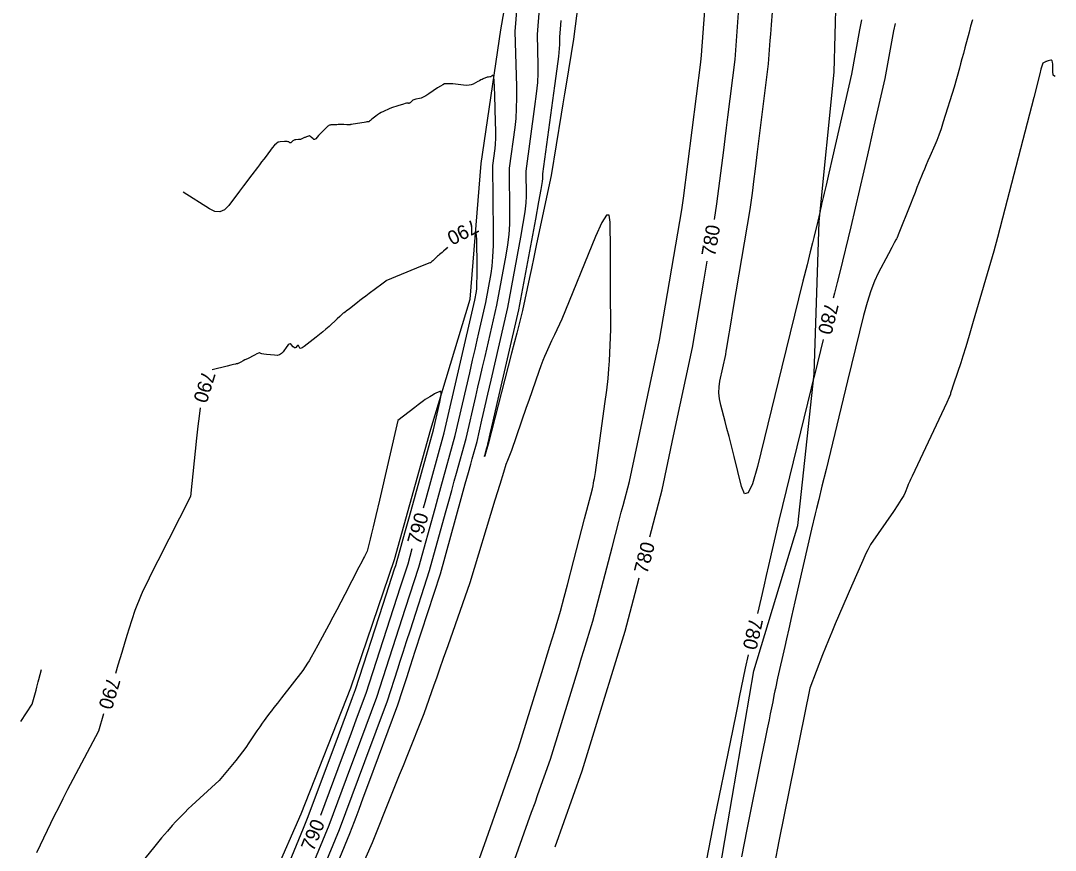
# Model space of a CAD drawing. Extents: x -26 to 1809989, y -25 to 828749.
# Drawn here: x 1809612.6 to 1809979.9, y 827324 to 827618.3 of the extents above; entities that cross this region are included whole.
import ezdxf

# ---------------------------------------------------------------- set-up
doc = ezdxf.new("R2010")
doc.units = 0
for name, color, linetype in [('DESIGN - CONTOURS - Index with Text', 7, 'Continuous'), ('DESIGN - CONTOURS - Intermediate with optional Text', 7, 'Continuous'), ('DESIGN - ROW - Slope Lines', 7, 'Continuous')]:
    doc.layers.add(name, color=color, linetype=linetype)

msp = doc.modelspace()

# ---------------------------------------------------------------- linework, layer by layer
at = {"layer": 'DESIGN - CONTOURS - Index with Text'}
for points in [[(1809858.86, 827547.81), (1809859.8, 827553.36), (1809862.18, 827572.38), (1809862.68, 827576.39), (1809863.17, 827580.29), (1809863.64, 827584.08), (1809866.22, 827604.57), (1809867.83, 827626.21), (1809868.17, 827630.65), (1809868.47, 827634.7), (1809868.74, 827638.36), (1809868.99, 827641.63), (1809869.41, 827647.21)], [(1809923.03, 827617.38), (1809922.5, 827614.75), (1809919.4, 827597.83), (1809915.52, 827580.87), (1809914.67, 827577.16), (1809913.78, 827573.29), (1809911.9, 827565.09), (1809907.33, 827545.22), (1809903.36, 827529.07), (1809902.49, 827525.49), (1809901.55, 827521.69), (1809901.1, 827519.84)], [(1809755.62, 827445.49), (1809756.19, 827447.55), (1809763, 827472.14), (1809773.83, 827519.15), (1809774.41, 827522.28), (1809774.52, 827523.32), (1809774.58, 827525.12), (1809774.61, 827527.67), (1809774.6, 827530.98), (1809774.53, 827540.8), (1809774.33, 827543.19)], [(1809764.17, 827537.96), (1809763.61, 827537.41), (1809762.74, 827536.59), (1809762.23, 827536.13), (1809761.3, 827535.37), (1809760.96, 827535.08), (1809760.6, 827534.78), (1809760.24, 827534.45), (1809759.88, 827534.11), (1809758.9, 827533.19), (1809758.58, 827532.88), (1809758.34, 827532.66), (1809758.19, 827532.52), (1809758.13, 827532.46), (1809758.08, 827532.42), (1809758.05, 827532.41), (1809758.03, 827532.4), (1809758, 827532.39), (1809757.96, 827532.39), (1809757.87, 827532.4), (1809757.54, 827532.28), (1809756.65, 827531.92), (1809755.18, 827531.32), (1809753.13, 827530.48), (1809742.26, 827525.99), (1809742.21, 827525.97), (1809742.2, 827525.96), (1809742.18, 827525.95), (1809740.76, 827524.88), (1809736.3, 827521.53), (1809735.1, 827520.62), (1809734, 827519.79), (1809733.01, 827519.03), (1809732.13, 827518.34), (1809729.93, 827516.61), (1809729.18, 827516.03), (1809728.6, 827515.58), (1809728.17, 827515.26), (1809727.91, 827515.07), (1809727.43, 827514.74), (1809727.13, 827514.51), (1809726.62, 827514.06), (1809725.88, 827513.39), (1809724.92, 827512.5), (1809722.07, 827509.85), (1809720.98, 827508.86), (1809719.86, 827507.89), (1809718.72, 827506.94), (1809717.54, 827506.01), (1809714.35, 827503.54), (1809713.29, 827502.77), (1809712.49, 827502.28), (1809711.96, 827502.09), (1809711.68, 827502.19), (1809711.31, 827502.85), (1809711.17, 827503.04), (1809711.02, 827503.11), (1809710.86, 827503.08), (1809710.7, 827502.94), (1809710.25, 827502.4), (1809710.07, 827502.26), (1809709.86, 827502.26), (1809709.63, 827502.38), (1809709.36, 827502.64), (1809708.62, 827503.49), (1809708.31, 827503.69), (1809707.95, 827503.62), (1809707.54, 827503.29), (1809707.08, 827502.71), (1809705.78, 827500.81), (1809705.22, 827500.2), (1809704.51, 827499.8), (1809703.67, 827499.6), (1809702.68, 827499.62), (1809699.86, 827499.94), (1809698.93, 827500.05), (1809698.25, 827500.15), (1809697.82, 827500.25), (1809697.65, 827500.33), (1809697.52, 827500.53), (1809697.37, 827500.54), (1809696.99, 827500.4), (1809696.38, 827500.13), (1809695.56, 827499.71), (1809693.06, 827498.42), (1809692.21, 827497.97), (1809691.54, 827497.62), (1809690.71, 827497.19), (1809690.08, 827496.85), (1809689.86, 827496.74), (1809689.67, 827496.66), (1809689.51, 827496.6), (1809689.39, 827496.58), (1809689.1, 827496.55), (1809688.82, 827496.5), (1809688.2, 827496.36), (1809687.24, 827496.13), (1809685.94, 827495.82), (1809680.55, 827494.52)], [(1809835.94, 827435.17), (1809840.29, 827451.86), (1809844.41, 827471.03), (1809851.16, 827502.42), (1809855.14, 827525.9), (1809856.35, 827533.02)], [(1809897.51, 827505.27), (1809894.51, 827493.04), (1809894.27, 827492.06), (1809893.99, 827490.93), (1809893.26, 827487.95), (1809881.78, 827440.98), (1809878.11, 827425.01), (1809877.3, 827421.46), (1809876.43, 827417.66), (1809875.5, 827413.6), (1809874.22, 827408.02)], [(1809676.37, 827480.97), (1809675.92, 827478.05), (1809675.46, 827474.43), (1809674.99, 827470.26), (1809672.83, 827449.54), (1809661.29, 827426.74), (1809659.06, 827422.32), (1809657.34, 827418.82), (1809656.11, 827416.25), (1809655.38, 827414.6), (1809653.14, 827409.06), (1809651.02, 827402.48), (1809650.43, 827400.62), (1809649.59, 827397.86), (1809648.49, 827394.2), (1809647.12, 827389.65), (1809646.26, 827386.76)], [(1809719.12, 827336.5), (1809726.81, 827357.1), (1809729.88, 827365.35), (1809731.87, 827370.68), (1809735.23, 827379.69), (1809747.47, 827417.45), (1809750.12, 827425.62), (1809751.62, 827431.03)], [(1809802.37, 827325.25), (1809811.98, 827352.24), (1809815.28, 827362.95), (1809827.23, 827401.77), (1809830.74, 827415.24), (1809832.15, 827420.66)], [(1809870.88, 827393.4), (1809869.78, 827388.6), (1809867.7, 827378.36), (1809867.16, 827375.72), (1809866.44, 827372.18), (1809864.45, 827362.41), (1809858.96, 827335.44), (1809856.09, 827320.79), (1809855.43, 827317.43), (1809854.68, 827313.61), (1809852.93, 827304.59), (1809851.13, 827295.37)], [(1809641.97, 827372.39), (1809640.16, 827366.31), (1809631.12, 827349.16), (1809629.26, 827345.59), (1809627.54, 827342.24), (1809625.96, 827339.11), (1809624.52, 827336.19), (1809618.16, 827323.09)]]:
    msp.add_lwpolyline(points, dxfattribs=at)
at = {"layer": 'DESIGN - CONTOURS - Intermediate with optional Text'}
for points in [[(1809783.47, 827307.9), (1809793.98, 827337.47), (1809795.19, 827340.86), (1809796.23, 827343.78), (1809800.68, 827356.28), (1809808.02, 827380.13), (1809810.72, 827388.92), (1809811.74, 827392.24), (1809812.54, 827394.84), (1809815.76, 827405.31), (1809822.56, 827431.4), (1809824.98, 827440.71), (1809825.83, 827443.96), (1809826.44, 827446.28), (1809828.69, 827454.9), (1809838.11, 827498.85), (1809839.43, 827504.96), (1809847.28, 827551.27), (1809847.97, 827555.39), (1809854.01, 827603.66), (1809854.31, 827606.08), (1809858.12, 827656.98)], [(1809706.9, 827285.55), (1809725.76, 827331.42), (1809734.76, 827355.54), (1809742.77, 827377), (1809746.46, 827388.39), (1809747.33, 827391.09), (1809748.37, 827394.3), (1809749.58, 827398.03), (1809750.96, 827402.27), (1809757.77, 827423.26), (1809763.43, 827443.72), (1809764.59, 827447.89), (1809765.62, 827451.62), (1809766.53, 827454.92), (1809767.32, 827457.78), (1809770.74, 827470.11), (1809774.16, 827484.99), (1809774.92, 827488.27), (1809775.72, 827491.73), (1809776.56, 827495.37), (1809777.44, 827499.19), (1809781.65, 827517.46), (1809784.92, 827535.11), (1809785.53, 827538.85), (1809785.96, 827542.53), (1809786.2, 827546.13), (1809786.27, 827549.66), (1809786.14, 827565.97), (1809788.11, 827580.4), (1809788.46, 827583.63), (1809788.68, 827587.13), (1809788.75, 827590.91), (1809788.69, 827594.95), (1809788.09, 827614.48), (1809790.79, 827646.8)], [(1809717.77, 827301.46), (1809729.47, 827329.91), (1809731.09, 827334.25), (1809731.67, 827335.81), (1809732.71, 827338.61), (1809734.23, 827342.67), (1809736.21, 827347.97), (1809746.53, 827375.65), (1809748.19, 827380.75), (1809748.73, 827382.44), (1809749.67, 827385.33), (1809750.99, 827389.41), (1809752.7, 827394.68), (1809761.59, 827422.07), (1809768.98, 827448.79), (1809770.42, 827453.96), (1809771.55, 827458.04), (1809772.37, 827461.02), (1809772.89, 827462.9), (1809774.6, 827469.09), (1809776.33, 827476.57), (1809776.81, 827478.67), (1809777.52, 827481.74), (1809778.45, 827485.8), (1809779.62, 827490.83), (1809785.56, 827516.62), (1809790.18, 827541.52), (1809791.04, 827546.43), (1809791.65, 827550.49), (1809792.01, 827553.68), (1809792.12, 827556.03), (1809792.05, 827564.96), (1809795.18, 827587.84), (1809795.75, 827592.43), (1809796.14, 827596.38), (1809796.35, 827599.71), (1809796.37, 827602.4), (1809796.02, 827613.47), (1809797.55, 827631.81)], [(1809810.51, 827624.65), (1809808.9, 827611.84), (1809806.25, 827595.86), (1809805.67, 827592.38), (1809805.08, 827588.81), (1809804.47, 827585.13), (1809800.88, 827563.45), (1809795.77, 827539.21), (1809794.76, 827534.42), (1809793.92, 827530.42), (1809793.25, 827527.22), (1809790.77, 827515.49), (1809789.19, 827509.32), (1809788.71, 827507.44), (1809787.94, 827504.44), (1809786.88, 827500.33), (1809778.6, 827468.04), (1809777.51, 827464.44), (1809777.33, 827463.85), (1809777.26, 827463.66), (1809777.3, 827463.85), (1809777.46, 827464.42), (1809778.02, 827466.45), (1809778.21, 827467.12), (1809778.34, 827467.61), (1809778.43, 827467.9), (1809778.45, 827468.01), (1809778.47, 827468.08), (1809778.49, 827468.16), (1809778.7, 827469.07), (1809779.32, 827471.75), (1809780.35, 827476.22), (1809781.79, 827482.47), (1809789.47, 827515.77), (1809795.43, 827547.94), (1809796.55, 827554.01), (1809797.35, 827558.45), (1809797.82, 827561.24), (1809797.98, 827562.39), (1809797.97, 827563.95), (1809802.24, 827595.28), (1809803.04, 827601.23), (1809803.61, 827605.64), (1809803.94, 827608.51), (1809804.04, 827609.84), (1809803.96, 827612.47), (1809804.32, 827616.82), (1809804.46, 827618.43)], [(1809911.1, 827618.64), (1809910.45, 827615.12), (1809907.55, 827599.33), (1809900.79, 827569.89), (1809899.49, 827564.26), (1809898.51, 827560), (1809897.84, 827557.09), (1809897.49, 827555.55), (1809896.96, 827553.25), (1809896.77, 827552.41), (1809896.59, 827551.63), (1809896.42, 827550.91), (1809896.27, 827550.24), (1809895.58, 827547.23), (1809894.14, 827541.41), (1809893.67, 827539.51), (1809892.88, 827536.29), (1809891.76, 827531.76), (1809890.32, 827525.91), (1809882.83, 827495.57), (1809874.17, 827460.2), (1809872.43, 827454.07), (1809870.9, 827450.83), (1809869.58, 827450.48), (1809868.49, 827453.03), (1809865.85, 827463.68), (1809864.92, 827467.45), (1809864.08, 827470.77), (1809863.34, 827473.65), (1809862.71, 827476.08), (1809861.15, 827481.97), (1809860.7, 827484.16), (1809860.49, 827486.3), (1809860.55, 827488.39), (1809860.85, 827490.44), (1809862.89, 827499.89), (1809863.09, 827501.08), (1809863.28, 827502.24), (1809863.79, 827505.2), (1809864.6, 827509.96), (1809865.71, 827516.52), (1809871.63, 827551.33), (1809872.25, 827556.3), (1809872.47, 827558.07), (1809872.87, 827561.24), (1809873.45, 827565.83), (1809874.2, 827571.82), (1809878.12, 827603.06), (1809878.74, 827611.26), (1809878.91, 827613.56), (1809879.16, 827616.92), (1809879.49, 827621.35)], [(1809950.46, 827618.59), (1809949.86, 827616.4), (1809949.29, 827614.27), (1809947.81, 827608.66), (1809947.27, 827606.64), (1809946.77, 827604.78), (1809946.31, 827603.08), (1809945.89, 827601.53), (1809944.02, 827594.71), (1809940.15, 827582.46), (1809939.34, 827579.98), (1809938.56, 827577.77), (1809937.82, 827575.83), (1809937.13, 827574.17), (1809935.31, 827570.11), (1809934.65, 827568.61), (1809934.02, 827567.14), (1809933.42, 827565.71), (1809932.86, 827564.31), (1809931.4, 827560.63), (1809930.8, 827559.13), (1809930.12, 827557.4), (1809929.33, 827555.42), (1809928.45, 827553.21), (1809924.14, 827542.34), (1809923.84, 827541.62), (1809923.78, 827541.48), (1809923.73, 827541.35), (1809923.67, 827541.25), (1809923.62, 827541.16), (1809923.5, 827540.95), (1809923.29, 827540.56), (1809922.75, 827539.55), (1809921.88, 827537.92), (1809920.68, 827535.66), (1809917.04, 827528.8), (1809915.69, 827525.93), (1809914.38, 827522.46), (1809913.1, 827518.39), (1809911.87, 827513.72), (1809906.18, 827490.52), (1809898.53, 827459.16), (1809897.06, 827453.14), (1809895.93, 827448.5), (1809895.14, 827445.25), (1809894.68, 827443.39), (1809893.36, 827437.94), (1809887.47, 827412.12), (1809886.3, 827406.98), (1809885.31, 827402.62), (1809884.49, 827399.04), (1809883.85, 827396.25), (1809881.29, 827385.04), (1809880.56, 827381.44), (1809880.38, 827380.56), (1809880.16, 827379.47), (1809879.9, 827378.18), (1809879.59, 827376.68), (1809878.72, 827372.39), (1809878.29, 827370.28), (1809877.65, 827367.14), (1809876.81, 827363), (1809875.76, 827357.83), (1809870.37, 827331.35), (1809868.48, 827321.68)], [(1809979.92, 827598.56), (1809979.3, 827598.85), (1809979.18, 827599.01), (1809979.1, 827599.36), (1809979.04, 827599.91), (1809979.02, 827600.65), (1809979, 827602.87), (1809978.95, 827603.59), (1809978.82, 827604.08), (1809978.6, 827604.33), (1809978.3, 827604.35), (1809977.38, 827604.08), (1809977.06, 827603.99), (1809976.81, 827603.9), (1809976.61, 827603.83), (1809976.47, 827603.77), (1809976.18, 827603.62), (1809975.96, 827603.5), (1809975.75, 827603.39), (1809975.47, 827603.24), (1809975.33, 827602.96), (1809975.1, 827602.25), (1809974.79, 827601.1), (1809974.39, 827599.52), (1809972.34, 827591.12), (1809961.99, 827551.46), (1809959.38, 827541.46), (1809958.09, 827536.53), (1809950.8, 827511.61), (1809949.35, 827506.69), (1809948.12, 827502.6), (1809947.11, 827499.34), (1809946.32, 827496.91), (1809943.92, 827489.74), (1809943.46, 827488.37), (1809943.15, 827487.43), (1809942.99, 827486.92), (1809942.75, 827486.13), (1809942.65, 827485.82), (1809942.53, 827485.49), (1809942.38, 827485.13), (1809942.22, 827484.75), (1809941.39, 827482.9), (1809929.04, 827456.68), (1809928.48, 827455.51), (1809928.26, 827455.02), (1809928.01, 827454.44), (1809927.73, 827453.78), (1809927.43, 827453.02), (1809926.58, 827450.89), (1809926.09, 827449.87), (1809925.23, 827448.43), (1809924.02, 827446.55), (1809922.46, 827444.24), (1809914.32, 827432.44), (1809913.56, 827431.13), (1809913.31, 827430.65), (1809912.91, 827429.78), (1809912.34, 827428.53), (1809911.62, 827426.87), (1809907.61, 827417.69), (1809901.78, 827404.34), (1809900.53, 827401.41), (1809899.36, 827398.6), (1809898.27, 827395.9), (1809897.27, 827393.31), (1809892.8, 827381.48), (1809881.79, 827327.27), (1809880.22, 827319.21)], [(1809703.22, 827287.11), (1809722.06, 827332.93), (1809728.23, 827349.48), (1809733.31, 827363.11), (1809739, 827378.34), (1809749.21, 827409.86), (1809753.94, 827424.44), (1809759.69, 827445.21), (1809760.7, 827448.82), (1809761.76, 827452.66), (1809766.87, 827471.12), (1809772, 827493.4), (1809773.03, 827497.87), (1809773.92, 827501.71), (1809774.66, 827504.94), (1809775.26, 827507.56), (1809777.74, 827518.31), (1809779.67, 827528.69), (1809780.02, 827531.27), (1809780.27, 827534.57), (1809780.4, 827538.58), (1809780.41, 827543.3), (1809780.23, 827566.99), (1809781.04, 827572.96), (1809781.18, 827574.52), (1809781.25, 827576.62), (1809781.25, 827579.28), (1809781.17, 827582.49), (1809780.89, 827591.77), (1809780.78, 827594.82), (1809780.67, 827597.01), (1809780.57, 827598.33), (1809780.47, 827598.79), (1809780.2, 827598.85), (1809780.1, 827598.86), (1809780.01, 827598.85), (1809779.94, 827598.81), (1809779.87, 827598.74), (1809779.71, 827598.54), (1809779.63, 827598.48), (1809779.52, 827598.43), (1809779.38, 827598.39), (1809779.21, 827598.38), (1809778.7, 827598.35), (1809778.49, 827598.33), (1809778.25, 827598.27), (1809777.97, 827598.18), (1809777.66, 827598.05), (1809776.8, 827597.68), (1809776.44, 827597.52), (1809776, 827597.31), (1809775.49, 827597.05), (1809774.9, 827596.74), (1809773.23, 827595.85), (1809772.55, 827595.58), (1809771.76, 827595.42), (1809770.86, 827595.37), (1809769.85, 827595.44), (1809767, 827595.77), (1809766.06, 827595.88), (1809765.38, 827595.95), (1809764.95, 827595.98), (1809764.78, 827595.98), (1809764.67, 827595.92), (1809764.62, 827595.9), (1809764.57, 827595.89), (1809764.5, 827595.88), (1809764.42, 827595.89), (1809764.2, 827595.91), (1809764.11, 827595.92), (1809764, 827595.93), (1809763.87, 827595.94), (1809763.72, 827595.95), (1809763.3, 827595.97), (1809763.02, 827595.89), (1809762.47, 827595.61), (1809761.68, 827595.13), (1809760.63, 827594.46), (1809757.48, 827592.4), (1809756.39, 827591.72), (1809755.48, 827591.21), (1809754.74, 827590.87), (1809754.19, 827590.7), (1809752.94, 827590.49), (1809752.5, 827590.39), (1809752.12, 827590.26), (1809751.81, 827590.09), (1809751.55, 827589.9), (1809750.94, 827589.33), (1809750.73, 827589.14), (1809750.58, 827589.01), (1809750.48, 827588.94), (1809750.42, 827588.93), (1809750.35, 827588.98), (1809750.31, 827588.99), (1809750.28, 827589.01), (1809750.23, 827589.03), (1809750.18, 827589.05), (1809750.03, 827589.09), (1809749.89, 827589.08), (1809749.58, 827589.02), (1809749.1, 827588.9), (1809748.45, 827588.72), (1809746.48, 827588.17), (1809745.74, 827587.95), (1809744.99, 827587.69), (1809744.22, 827587.39), (1809743.45, 827587.06), (1809741.38, 827586.12), (1809740.63, 827585.75), (1809739.94, 827585.37), (1809739.31, 827584.96), (1809738.73, 827584.52), (1809737.27, 827583.34), (1809736.78, 827582.95), (1809736.4, 827582.67), (1809736.14, 827582.5), (1809735.98, 827582.45), (1809735.7, 827582.44), (1809735.5, 827582.43), (1809735.11, 827582.37), (1809734.53, 827582.27), (1809733.75, 827582.14), (1809731.42, 827581.74), (1809730.65, 827581.6), (1809730.08, 827581.51), (1809729.71, 827581.45), (1809729.55, 827581.43), (1809729.38, 827581.43), (1809729.28, 827581.43), (1809729.08, 827581.43), (1809728.8, 827581.43), (1809728.43, 827581.43), (1809727.31, 827581.45), (1809726.94, 827581.45), (1809726.64, 827581.45), (1809726.42, 827581.46), (1809726.28, 827581.47), (1809726.02, 827581.48), (1809725.87, 827581.48), (1809725.61, 827581.48), (1809725.26, 827581.46), (1809724.81, 827581.44), (1809723.47, 827581.38), (1809723.02, 827581.36), (1809722.67, 827581.33), (1809722.42, 827581.3), (1809722.28, 827581.27), (1809722.02, 827581.18), (1809721.88, 827581.09), (1809721.62, 827580.87), (1809721.25, 827580.53), (1809720.77, 827580.06), (1809718.29, 827577.59), (1809717.33, 827576.44), (1809717.12, 827576.25), (1809716.9, 827576.18), (1809716.66, 827576.23), (1809716.41, 827576.39), (1809715.74, 827576.99), (1809715.51, 827577.19), (1809715.35, 827577.33), (1809715.26, 827577.42), (1809715.22, 827577.45), (1809715.22, 827577.47), (1809715.18, 827577.47), (1809715.09, 827577.44), (1809714.95, 827577.4), (1809714.74, 827577.33), (1809714.12, 827577.12), (1809713.88, 827577.03), (1809713.64, 827576.94), (1809713.4, 827576.84), (1809713.14, 827576.73), (1809712.46, 827576.42), (1809712.19, 827576.32), (1809711.9, 827576.24), (1809711.58, 827576.18), (1809711.23, 827576.15), (1809710.28, 827576.09), (1809709.94, 827576.05), (1809709.66, 827575.97), (1809709.42, 827575.85), (1809709.23, 827575.68), (1809708.78, 827575.19), (1809708.61, 827575.04), (1809708.45, 827574.97), (1809708.3, 827574.96), (1809708.15, 827575.03), (1809707.76, 827575.3), (1809707.55, 827575.39), (1809707.24, 827575.44), (1809706.81, 827575.47), (1809706.27, 827575.46), (1809704.69, 827575.39), (1809704.06, 827575.23), (1809703.39, 827574.81), (1809702.65, 827574.13), (1809701.87, 827573.18), (1809699.69, 827570.31), (1809698.89, 827569.25), (1809698.11, 827568.21), (1809697.35, 827567.2), (1809696.61, 827566.22), (1809694.67, 827563.65), (1809693.85, 827562.57), (1809692.86, 827561.25), (1809691.68, 827559.69), (1809690.33, 827557.89), (1809686.48, 827552.79), (1809684.97, 827551.27), (1809683.31, 827550.56), (1809681.52, 827550.64), (1809679.59, 827551.53), (1809670.24, 827557.53)], [(1809772.35, 827312.43), (1809777.92, 827328.08), (1809783.03, 827342.45), (1809789.38, 827360.32), (1809797.61, 827387.1), (1809800.49, 827396.47), (1809802.09, 827401.66), (1809804.3, 827408.86), (1809805.59, 827413.81), (1809806.72, 827418.15), (1809809, 827426.92), (1809812.82, 827441.57), (1809814.07, 827446.42), (1809814.99, 827449.99), (1809815.57, 827452.28), (1809815.81, 827453.29), (1809815.99, 827454.27), (1809816.13, 827455.05), (1809816.29, 827455.92), (1809816.67, 827458.06), (1809820.02, 827482.4), (1809820.65, 827487.26), (1809821.14, 827491.42), (1809821.46, 827494.86), (1809821.63, 827497.6), (1809822.06, 827508.72), (1809822.02, 827523.36), (1809822, 827526.57), (1809821.99, 827529.92), (1809821.97, 827533.4), (1809821.94, 827537.03), (1809821.88, 827546.89), (1809821.53, 827549.34), (1809820.55, 827549.3), (1809818.93, 827546.77), (1809816.68, 827541.74), (1809804.66, 827512.48), (1809802.09, 827506.89), (1809801.1, 827504.75), (1809799.14, 827500.53), (1809798.58, 827499.25), (1809797.96, 827497.72), (1809797.28, 827495.93), (1809796.56, 827493.89), (1809792.95, 827483.53), (1809792.08, 827481.04), (1809786.79, 827465.9), (1809785.37, 827462.34), (1809784.87, 827460.89), (1809783.96, 827458.05), (1809782.65, 827453.83), (1809780.94, 827448.23), (1809772.03, 827418.84), (1809764.19, 827396.53), (1809762.62, 827392.07), (1809761.28, 827388.26), (1809760.17, 827385.1), (1809759.29, 827382.59), (1809755.69, 827372.37), (1809749.64, 827357.28), (1809748.33, 827354), (1809746.97, 827350.63), (1809745.58, 827347.15), (1809744.14, 827343.58), (1809737.37, 827326.69), (1809732.43, 827315.46)], [(1809695.85, 827290.23), (1809712.96, 827331.83), (1809714.65, 827335.95), (1809725.38, 827364.72), (1809729.94, 827376.95), (1809730.42, 827378.25), (1809731.47, 827381.04), (1809741.28, 827411.31), (1809745.36, 827423.89), (1809745.73, 827425.03), (1809746.3, 827426.8), (1809746.78, 827428.53), (1809749.02, 827436.63), (1809750.63, 827442.43), (1809759.13, 827473.15), (1809761.4, 827483.02), (1809761.77, 827484.84), (1809761.88, 827486.08), (1809761.75, 827486.72), (1809761.37, 827486.78), (1809760.03, 827486.17), (1809759.52, 827485.92), (1809758.98, 827485.62), (1809758.42, 827485.29), (1809757.83, 827484.92), (1809756.24, 827483.88), (1809755.56, 827483.41), (1809754.71, 827482.79), (1809753.69, 827482.02), (1809752.5, 827481.1), (1809746.54, 827476.46), (1809739.98, 827448.24), (1809738.72, 827442.84), (1809737.75, 827438.72), (1809737.08, 827435.89), (1809736.69, 827434.35), (1809735.57, 827430.13), (1809734.66, 827428.29), (1809734.31, 827427.61), (1809733.66, 827426.34), (1809732.7, 827424.49), (1809727.66, 827414.79), (1809726.24, 827412.07), (1809724.81, 827409.36), (1809723.38, 827406.66), (1809721.95, 827403.97), (1809718.1, 827396.82), (1809716.8, 827394.4), (1809715.76, 827392.52), (1809714.98, 827391.16), (1809714.47, 827390.34), (1809712.72, 827387.74), (1809705.19, 827378.09), (1809703.72, 827376.19), (1809702.52, 827374.65), (1809701.61, 827373.46), (1809700.97, 827372.63), (1809699.65, 827370.87), (1809699.08, 827370.09), (1809698.36, 827369.08), (1809697.5, 827367.83), (1809696.48, 827366.35), (1809693.58, 827362.09), (1809692.48, 827360.51), (1809691.33, 827358.94), (1809690.14, 827357.4), (1809688.92, 827355.87), (1809683.1, 827348.8), (1809676.17, 827342.55), (1809674.72, 827341.23), (1809673.36, 827339.94), (1809672.07, 827338.68), (1809670.86, 827337.46), (1809667.73, 827334.24), (1809666.38, 827332.78), (1809664.67, 827330.82), (1809662.6, 827328.37), (1809660.17, 827325.41), (1809648.02, 827310.46)], [(1809612.59, 827369.68), (1809616.7, 827375.87), (1809618.06, 827380.86), (1809618.33, 827381.89), (1809618.59, 827382.85), (1809618.82, 827383.74), (1809619.02, 827384.55), (1809619.93, 827388.18)]]:
    msp.add_lwpolyline(points, dxfattribs=at)
at = {"layer": 'DESIGN - ROW - Slope Lines'}
for p, q in [((1809783.11, 827615.11), (1809791.39, 827662.51)), ((1809901.36, 827600.12), (1809902.93, 827653.27)), ((1809776.05, 827567.7), (1809783.11, 827615.11)), ((1809896.13, 827547.14), (1809901.36, 827600.12)), ((1809772.15, 827519.52), (1809776.05, 827567.7)), ((1809894.32, 827493.08), (1809896.13, 827547.14)), ((1809758.18, 827473.4), (1809772.15, 827519.52)), ((1809888.53, 827439.21), (1809894.32, 827493.08)), ((1809745.25, 827427.13), (1809758.18, 827473.4)), ((1809872.85, 827387.65), (1809888.53, 827439.21)), ((1809729.77, 827381.64), (1809745.25, 827427.13)), ((1809863.66, 827333.75), (1809872.85, 827387.65)), ((1809712.14, 827336.97), (1809729.77, 827381.64)), ((1809692.33, 827291.71), (1809712.14, 827336.97)), ((1809854.25, 827279.05), (1809863.66, 827333.75))]:
    msp.add_line(p, q, dxfattribs=at)

# ---------------------------------------------------------------- texts
at = {"layer": 'DESIGN - CONTOURS - Index with Text'}
for s, rotation, p in [('790', 207.2362, (1809773.39, 827548.04)), ('780', 80.3548, (1809859.12, 827534.42)), ('780', 256.189, (1809898.23, 827518.64)), ('790', 252.8418, (1809677.12, 827494.47)), ('790', 74.5267, (1809754.52, 827432.14)), ('780', 75.377, (1809835.04, 827421.81)), ('780', 257.1274, (1809871.37, 827406.78)), ('790', 253.3839, (1809643.34, 827385.71)), ('790', 67.9237, (1809716.53, 827323.35))]:
    msp.add_text(s, height=5, rotation=rotation, dxfattribs=at).set_placement(p)

doc.saveas('drawing.dxf')
